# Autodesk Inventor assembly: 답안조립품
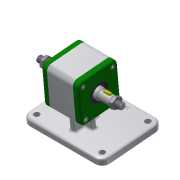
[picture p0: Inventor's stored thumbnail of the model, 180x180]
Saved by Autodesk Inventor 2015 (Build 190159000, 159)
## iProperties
Created: 2020-11
Part Number: 답안조립품
Document SubType Name: Assembly
Designer: pc-04
Author: pc-04
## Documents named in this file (10)
- C:\Users\pc-04\Desktop\답안조립품.iam
- C:\Users\pc-04\AppData\Local\Temp\Temp1_701106V1044.zip\1.본체.ipt
- C:\Users\pc-04\Desktop\너트 M10x1.ipt
- C:\Users\pc-04\Desktop\베어링 6004.ipt
- C:\Users\pc-04\Desktop\볼트 M4.ipt
- C:\Users\pc-04\Desktop\오일 실 17 30 5.ipt
- C:\Users\pc-04\Desktop\축.ipt
- C:\Users\pc-04\Desktop\커버.ipt
- C:\Users\pc-04\Desktop\키 5 x 5 x 12.ipt
- C:\Users\pc-04\Desktop\V-벨트풀리.ipt
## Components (3 placed, 2 different names)
1. 1.본체:1
2. V-벨트풀리:1 — 각도:2
3. V-벨트풀리:2
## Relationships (1: Angle 1)
- 각도:2 [Angle]: V-벨트풀리:1
